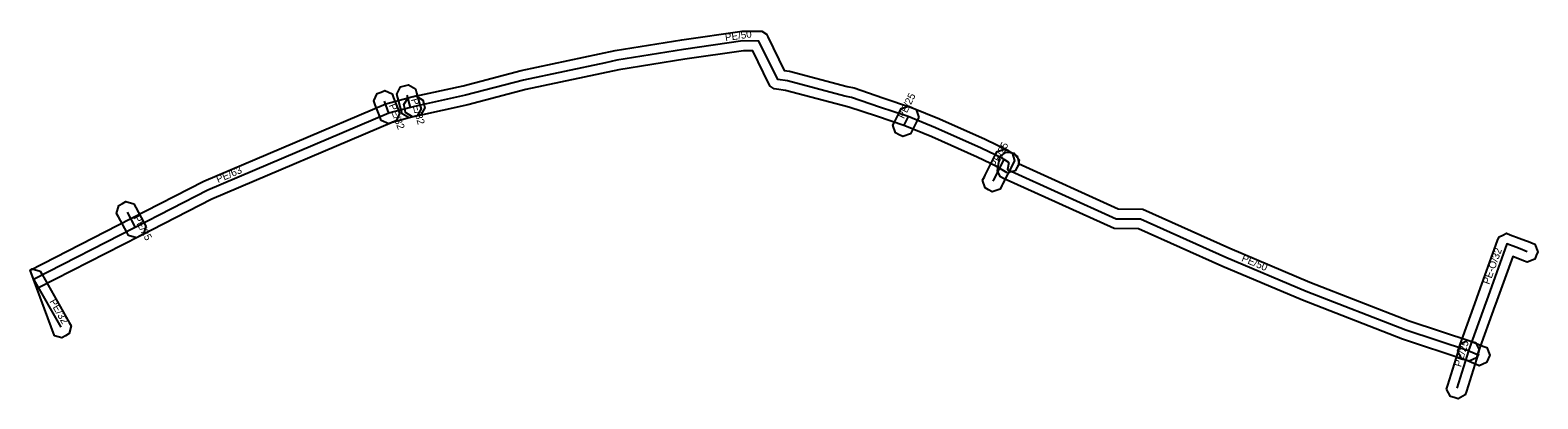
# Model space of a CAD drawing. Extents: x -686745 to -686591, y -1053758 to -1053720.
import ezdxf

# ---------------------------------------------------------------- set-up
doc = ezdxf.new("R2010")
doc.units = 0
for name, color, linetype in [('1', 7, 'Continuous'), ('24', 7, 'Continuous'), ('30', 7, 'Continuous')]:
    doc.layers.add(name, color=color, linetype=linetype)

msp = doc.modelspace()

# ---------------------------------------------------------------- linework, layer by layer
at = {"layer": '1'}
for points in [[(-686645.31, -1053734.64), (-686645.67, -1053734.43), (-686646.23, -1053734.1), (-686646.32, -1053734.03), (-686648.39, -1053733.03), (-686653.02, -1053730.97), (-686655.77, -1053729.85), (-686658.65, -1053728.88), (-686661.46, -1053727.93), (-686662.12, -1053727.79), (-686667.92, -1053726.24), (-686668.85, -1053726.12), (-686669.1, -1053726.09), (-686669.51, -1053725.8), (-686669.62, -1053725.57), (-686671.27, -1053722.21), (-686672.22, -1053722.2), (-686678.2, -1053723.06), (-686684.95, -1053724.15), (-686694.43, -1053726.16), (-686700.35, -1053727.71), (-686705.59, -1053728.85), (-686705.99, -1053728.94), (-686706.69, -1053728.49), (-686706.78, -1053728.08), (-686706.86, -1053727.68), (-686706.42, -1053726.98), (-686706.01, -1053726.89), (-686700.81, -1053725.77), (-686694.89, -1053724.22), (-686685.31, -1053722.19), (-686678.5, -1053721.08), (-686672.36, -1053720.2), (-686670.64, -1053720.21), (-686670.36, -1053720.21), (-686669.88, -1053720.51), (-686669.75, -1053720.77), (-686668.06, -1053724.21), (-686667.53, -1053724.28), (-686661.66, -1053725.85), (-686660.94, -1053725.99), (-686658.01, -1053726.98), (-686655.07, -1053727.97), (-686652.24, -1053729.13), (-686647.55, -1053731.21), (-686645.19, -1053732.35), (-686645.05, -1053732.48), (-686644.66, -1053732.71), (-686644.3, -1053732.91), (-686644.09, -1053733.72), (-686644.3, -1053734.07), (-686644.51, -1053734.43), (-686645.31, -1053734.64)], [(-686744.29, -1053746.43), (-686745, -1053744.54), (-686734.72, -1053739.3), (-686727.29, -1053735.5), (-686708.71, -1053727.6), (-686706.44, -1053727), (-686706.05, -1053726.9), (-686705.65, -1053726.8), (-686704.93, -1053727.22), (-686704.83, -1053727.62), (-686704.73, -1053728.02), (-686705.15, -1053728.74), (-686705.55, -1053728.84), (-686705.94, -1053728.94), (-686708.07, -1053729.5), (-686726.45, -1053737.32), (-686733.81, -1053741.08), (-686744.2, -1053746.38), (-686744.29, -1053746.43)], [(-686709.18, -1053729.29), (-686709.33, -1053728.91), (-686709.79, -1053727.7), (-686709.93, -1053727.31), (-686709.59, -1053726.55), (-686709.2, -1053726.41), (-686708.82, -1053726.26), (-686708.06, -1053726.6), (-686707.92, -1053726.99), (-686707.45, -1053728.2), (-686707.31, -1053728.58), (-686707.65, -1053729.34), (-686708.04, -1053729.49), (-686708.42, -1053729.63), (-686709.18, -1053729.29)], [(-686707.04, -1053728.64), (-686707.15, -1053728.24), (-686707.49, -1053727.01), (-686707.6, -1053726.61), (-686707.2, -1053725.89), (-686706.8, -1053725.78), (-686706.4, -1053725.67), (-686705.68, -1053726.07), (-686705.57, -1053726.47), (-686705.23, -1053727.7), (-686705.12, -1053728.1), (-686705.53, -1053728.82), (-686705.92, -1053728.93), (-686706.32, -1053729.04), (-686707.04, -1053728.64)], [(-686654.34, -1053728.99), (-686654.53, -1053729.36), (-686655, -1053730.31), (-686655.19, -1053730.68), (-686655.97, -1053730.95), (-686656.35, -1053730.76), (-686656.72, -1053730.57), (-686656.98, -1053729.79), (-686656.79, -1053729.42), (-686656.31, -1053728.46), (-686656.13, -1053728.09), (-686655.34, -1053727.83), (-686654.97, -1053728.02), (-686654.6, -1053728.2), (-686654.34, -1053728.99)], [(-686647.83, -1053735.4), (-686647.64, -1053735.03), (-686647.58, -1053734.89), (-686646.53, -1053732.84), (-686646.34, -1053732.47), (-686645.56, -1053732.21), (-686645.19, -1053732.4), (-686644.82, -1053732.59), (-686644.56, -1053733.37), (-686644.75, -1053733.74), (-686645.79, -1053735.8), (-686645.86, -1053735.94), (-686646.05, -1053736.31), (-686646.84, -1053736.56), (-686647.21, -1053736.37), (-686647.58, -1053736.18), (-686647.83, -1053735.4)], [(-686644.11, -1053733.31), (-686644.17, -1053733.69), (-686633.98, -1053738.32), (-686631.48, -1053738.33), (-686622.61, -1053742.32), (-686614.43, -1053745.76), (-686604.3, -1053749.7), (-686597.91, -1053751.81), (-686597.84, -1053751.84), (-686596.78, -1053752.28), (-686596.39, -1053752.44), (-686596.08, -1053753.21), (-686596.24, -1053753.59), (-686596.4, -1053753.97), (-686597.16, -1053754.29), (-686597.54, -1053754.13), (-686598.61, -1053753.69), (-686598.62, -1053753.69), (-686604.98, -1053751.58), (-686615.18, -1053747.62), (-686623.41, -1053744.16), (-686631.92, -1053740.33), (-686634.42, -1053740.32), (-686645.68, -1053735.2), (-686645.99, -1053735.06), (-686646.31, -1053734.47), (-686646.26, -1053734.14), (-686646.15, -1053733.42), (-686646.09, -1053733.01), (-686645.42, -1053732.52), (-686645.01, -1053732.58), (-686644.6, -1053732.64), (-686644.11, -1053733.31)], [(-686734.43, -1053737.81), (-686734.23, -1053738.17), (-686733.39, -1053739.71), (-686733.19, -1053740.07), (-686733.42, -1053740.87), (-686733.79, -1053741.06), (-686734.15, -1053741.26), (-686734.95, -1053741.03), (-686735.14, -1053740.67), (-686735.99, -1053739.13), (-686736.19, -1053738.77), (-686735.95, -1053737.97), (-686735.59, -1053737.77), (-686735.23, -1053737.57), (-686734.43, -1053737.81)], [(-686593.16, -1053743.39), (-686593.74, -1053743.17), (-686595.49, -1053748), (-686595.56, -1053748.2), (-686597.22, -1053752.79), (-686597.32, -1053753.08), (-686597.45, -1053753.47), (-686598.2, -1053753.83), (-686598.59, -1053753.7), (-686598.98, -1053753.56), (-686599.34, -1053752.81), (-686599.2, -1053752.42), (-686599.1, -1053752.13), (-686597.44, -1053747.52), (-686597.37, -1053747.32), (-686595.28, -1053741.54), (-686595.14, -1053741.15), (-686594.76, -1053740.97), (-686594.38, -1053740.8), (-686593.99, -1053740.95), (-686593.09, -1053741.28), (-686592.45, -1053741.52), (-686592.12, -1053741.64), (-686591.88, -1053741.75), (-686591.49, -1053741.91), (-686591.18, -1053742.67), (-686591.34, -1053743.05), (-686591.5, -1053743.44), (-686592.26, -1053743.75), (-686592.65, -1053743.59), (-686592.88, -1053743.5), (-686593.16, -1053743.39)], [(-686742.5, -1053751.23), (-686745, -1053744.54), (-686744.78, -1053744.42), (-686743.99, -1053744.64), (-686743.78, -1053745), (-686741.01, -1053749.87), (-686740.81, -1053750.23), (-686741.03, -1053751.02), (-686741.39, -1053751.23), (-686741.75, -1053751.43), (-686742.5, -1053751.23)], [(-686600.49, -1053756.68), (-686600.36, -1053756.28), (-686599.18, -1053752.47), (-686599.06, -1053752.07), (-686598.33, -1053751.69), (-686597.93, -1053751.81), (-686597.54, -1053751.93), (-686597.15, -1053752.66), (-686597.27, -1053753.06), (-686598.45, -1053756.88), (-686598.58, -1053757.27), (-686599.31, -1053757.66), (-686599.71, -1053757.53), (-686600.1, -1053757.41), (-686600.49, -1053756.68)]]:
    msp.add_lwpolyline(points, dxfattribs=at)
at = {"layer": '24'}
for points in [[(-686655.42, -1053728.91), (-686658.33, -1053727.93), (-686661.2, -1053726.96), (-686661.89, -1053726.82), (-686667.72, -1053725.26), (-686668.72, -1053725.13), (-686670.65, -1053721.21), (-686672.29, -1053721.2), (-686678.35, -1053722.07), (-686685.13, -1053723.17), (-686686.31, -1053723.42)], [(-686686.31, -1053723.42), (-686694.66, -1053725.19), (-686700.58, -1053726.74), (-686705.8, -1053727.87)], [(-686706.19, -1053727.97), (-686706.53, -1053726.74)], [(-686708.39, -1053728.55), (-686708.85, -1053727.34)], [(-686706.19, -1053727.97), (-686708.39, -1053728.55)], [(-686705.8, -1053727.87), (-686706.19, -1053727.97)], [(-686708.39, -1053728.55), (-686726.87, -1053736.41), (-686734.27, -1053740.19)], [(-686655.42, -1053728.91), (-686655.9, -1053729.86)], [(-686645.64, -1053733.29), (-686645.75, -1053733.19), (-686647.97, -1053732.12), (-686652.63, -1053730.05), (-686655.42, -1053728.91)], [(-686646.75, -1053735.48), (-686646.69, -1053735.35), (-686645.64, -1053733.29)], [(-686645.16, -1053733.57), (-686645.64, -1053733.29)], [(-686645.16, -1053733.57), (-686645.27, -1053734.29), (-686634.2, -1053739.32), (-686631.7, -1053739.33), (-686623.01, -1053743.24), (-686614.8, -1053746.69), (-686604.64, -1053750.64), (-686598.26, -1053752.75)], [(-686735.11, -1053738.65), (-686734.27, -1053740.19)], [(-686734.27, -1053740.19), (-686744.64, -1053745.49)], [(-686592.8, -1053742.45), (-686593.44, -1053742.22), (-686594.34, -1053741.88), (-686596.43, -1053747.66), (-686596.5, -1053747.86)], [(-686592.26, -1053742.67), (-686592.5, -1053742.57), (-686592.8, -1053742.45)], [(-686744.63, -1053745.53), (-686741.88, -1053750.36)], [(-686596.5, -1053747.86), (-686598.16, -1053752.46), (-686598.26, -1053752.75)], [(-686599.41, -1053756.58), (-686598.23, -1053752.76)], [(-686598.26, -1053752.75), (-686598.23, -1053752.76)], [(-686598.23, -1053752.76), (-686597.16, -1053753.21)]]:
    msp.add_lwpolyline(points, dxfattribs=at)

# ---------------------------------------------------------------- texts
at = {"layer": '30'}
for s, rotation, p in [('PE/50', 8.1698, (-686674.05, -1053721.22)), ('PE/25', 63.411, (-686655.86, -1053729.19)), ('PE/32', 290.8151, (-686708.42, -1053727.75)), ('PE/32', 285.452, (-686706.16, -1053727.16)), ('PE/25', 63.0685, (-686646.4, -1053734.19)), ('PE/63', 23.0412, (-686725.83, -1053735.68)), ('PE/25', 298.7278, (-686734.49, -1053739.22)), ('PE-O/32', 70.1204, (-686596.13, -1053746.07)), ('PE/50', 337.2069, (-686621.47, -1053743.6)), ('PE/32', 299.6307, (-686743.05, -1053747.74)), ('PE/25', 72.8077, (-686599.02, -1053754.47))]:
    msp.add_text(s, height=0.75, rotation=rotation, dxfattribs=at).set_placement(p)

doc.saveas('drawing.dxf')
